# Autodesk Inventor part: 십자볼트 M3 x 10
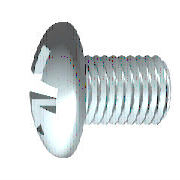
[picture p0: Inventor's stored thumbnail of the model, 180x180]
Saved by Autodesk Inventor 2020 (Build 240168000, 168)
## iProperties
Created: 2012-02
Part Number: 십자볼트 M3 x 10
Material: 스테인리스강
Description: 십자 오목 머리 나사
Document SubType Name: Modeling
Standard: KS B 1023
Designer: mduedu
Standards Organization: KS
Language: ko-KR
Size Designation: A  M 3 x 10 - H
Categories: <MemberInstance><Categories><Category DisplayName="조임쇠" InternalName="e4da775c-781d-43d5-af7c-5136215cf5a6" Mnemonic="FSTN"><Category DisplayName="볼트" InternalN
Density: 1 g/cm^3
Appearance: 반광택
IsCustomPart: 0
Author: mduedu
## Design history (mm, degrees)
body "Solid1"
workplane "Work Plane3"
sketch "스케치2"
  geometry: L1 (-3.72, 0)-(3.72, 0) reference; L2 (0, -3.72)-(0, 3.72) reference; L3 (0, 1.5)-(0, 0); L4 (0, 0)-(1.5, 0); L5 (0, 0)-(1.879, 1.879); L6 (0.253, 1.479)-(0.261, 0.456); L7 (1.479, 0.253)-(0.456, 0.261); L8 (0.253, -1.479)-(0.261, -0.456); L9 (1.479, -0.253)-(0.456, -0.261); L10 (-0.253, 1.479)-(-0.261, 0.456); L11 (-1.479, 0.253)-(-0.456, 0.261); L12 (-1.479, -0.253)-(-0.456, -0.261); L13 (-0.253, -1.479)-(-0.261, -0.456); A1 r 0.45 centre (0, 0) between (0.45, 0) and (0, 0.45); A2 r 1.5 centre (0, 0) between (1.5, 0) and (1.479, 0.253); A3 r 1.5 centre (0, 0) between (0.253, 1.479) and (0, 1.5); A4 r 1.5 centre (0, 0) between (1.479, 0.253) and (0.253, 1.479); A5 r 1.5 centre (0, 0) between (0, -1.5) and (0.253, -1.479); A6 r 1.5 centre (0, 0) between (0.253, -1.479) and (1.479, -0.253); A7 r 1.5 centre (0, 0) between (1.479, -0.253) and (1.5, 0); A8 r 1.5 centre (0, 0) between (-1.479, 0.253) and (-1.5, 0); A9 r 1.5 centre (0, 0) between (-0.253, 1.479) and (-1.479, 0.253); A10 r 1.5 centre (0, 0) between (0, 1.5) and (-0.253, 1.479); A11 r 1.5 centre (0, 0) between (-1.5, 0) and (-1.479, -0.253); A12 r 1.5 centre (0, 0) between (-1.479, -0.253) and (-0.253, -1.479); A13 r 1.5 centre (0, 0) between (-0.253, -1.479) and (0, -1.5); A14 r 0.525 centre (0, 0) between (0.525, 0) and (0, 0.525); A15 r 0.197 centre (0.457, 0.457) between (0.261, 0.456) and (0.456, 0.261); A16 r 0.197 centre (0.457, -0.457) between (0.456, -0.261) and (0.261, -0.456); A17 r 0.197 centre (-0.457, 0.457) between (-0.456, 0.261) and (-0.261, 0.456); A18 r 0.197 centre (-0.457, -0.457) between (-0.261, -0.456) and (-0.456, -0.261); 1 further point
  constraints: 38 point on circle, 22 end point, 19 symmetric about line, 18 centre point, 4 coincident, 3 collinear, 3 point on line, 3 tangent, 1 perpendicular, 21 other
  dimensions: "d4" = 45 deg angle of L5 L4; "d5" = 0.9 diameter of A1 (= 0.3 x SDM); "d6" = 3 diameter of A4 (= SDM); "d7" = 0.2525 distance from line of L6.start L3 (= 0.5 x SBR); "d14" = 1.05 diameter of A14 (= 0.35 x SDM)
extrude "슬롯" join sketch "스케치2" taper "d15" = 5 deg; stored distance "d54" = 10
revolve "절단부" stored, may be unused: angle "d56" = 90 deg
revolve "본체" stored, may be unused: angle "d18" = 90 deg
workplane "Work Plane1"
sketch "스케치1"
  geometry: L1 (10, 0)-(10, 1.5); L2 (10, 1.5)-(1, 1.5); L3 (3.962, 5.08)-(3.962, 5.08); L4 (-2.4, 0)-(-2.4, 2.59); L5 (-2.2, 1.4)-(-1.036, 0.82); L6 (-1.036, 0.82)-(-0.6, 0); L7 (-0.6, 0)-(10, 0); L8 (-5.105, 0)-(12.517, 0) reference; L9 (0, -1.016)-(0, 6.096) reference; L10 (-2.2, 1.4)-(-2.4, 1.5); L11 (-1.636, 2.657)-(-2.4, 2.59); L12 (-1.636, 2.657)-(0, 2.8); L13 (0, 2.8)-(0, 1.347); L14 (0, 1.347)-(0.693, 1.347); L15 (0.693, 1.347)-(1, 1.5); L16 (1, 1.5)-(0, 1.5); A1 r 5 centre (2.6, 0) between (-1.636, 2.657) and (-2.4, 0)
  constraints: 28 end point, 5 point on line, 4 collinear, 4 point on circle, 3 parallel, 2 perpendicular, 1 centre point, 1 horizontal, 1 tangent
  dimensions: "d1" = 3 diameter of L2 L7 (= GD); "d2" = 1.8 distance from line of L6.end L4 (= STI); "d11" = 3 diameter of L10.end L7 (= SDM); "d12" = 62 deg angle of L6 L7; "d13" = 26.5 deg angle of L5 L7; "d17" = 5.6 diameter of L12.end L7 (= KOD); "d19" = 5 deg angle of L12 L7 (= KEWI); "d20" = 2.4 distance between parallel lines of L4 L13 (= KOH); "d21" = 5 radius of A1 (= KR); "d23" = 2.6935 diameter of L14 L7 (= BDM); "d24" = 9 distance of L1.end L2.end (= GEL); "d25" = 0.30673 horizontal distance of L14.end L2.end (= GAL); "d28" = 10 distance between parallel lines of L1 L13 (= NLG)
fillet "모깎기1" dims "d29" = 1.2 (= RR)
fillet "모깎기2" dims "d16" = 0.101 (= 0.2 x SBR)
feature "스레드" dims "d8" = 9 (= GEL), "d9" = 0
chamfer "모따기1" distance "d26" = 0.30673 (= -0.5 x SPD + 0.5 x GD); stored, may be unused: second distance "d27" = 0.30683 (computed from GUL), angle "d78" = 45 deg
other parameters: "GD" = 3 (= NND) [user parameter; used in 2 equation terms], "NLG" = 10 [user parameter; used in 1 equation term], "GEL" = 9 [user parameter; used in 2 equation terms], "KOD" = 5.6 [user parameter; used in 1 equation term], "KOH" = 2.4 [user parameter; used in 2 equation terms], "SDM" = 3 [user parameter; used in 4 equation terms], "STI" = 1.8 [user parameter; used in 1 equation term], "SBR" = 0.505 [user parameter; used in 2 equation terms], "GAL" = 0.30673 (= 0.61345 x PTC) [user parameter; used in 1 equation term], "SPD" = 2.38655 (= NND - 1.2269 x PTC) [user parameter; used in 1 equation term], "KEWI" = 5 deg [user parameter; used in 1 equation term], "d3" = -2.4 (= -KOH), "d10" = 0, "KR" = 5 [user parameter; used in 1 equation term], "BDM" = 2.6935 [user parameter; used in 1 equation term], "GUL" = 0.30673 (= 0.61345 x PTC) [user parameter; used in 1 equation term], "RR" = 1.2 [user parameter; used in 1 equation term], "d79" = 0, "d80" = 0, "PTC" = 0.5 [user parameter; used in 5 equation terms], "THREADDIA" = 3 [user parameter; used in 1 equation term], "TOA" = 30 deg [user parameter], "NND" = 3 [user parameter; used in 2 equation terms], "GD1" = 2.38655 (= THREADDIA - 1.2269 x PTC) [user parameter]
